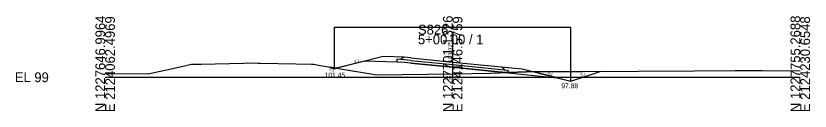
# Model space of a CAD drawing. Extents: x 2118382 to 2118616, y 1213030 to 1222057.
# Drawn here: x 2118381.9 to 2118610.4, y 1215530.1 to 1215557.4 of the extents above; entities that cross this region are included whole.
import ezdxf

# ---------------------------------------------------------------- set-up
doc = ezdxf.new("R2010")
doc.units = 0
for name, color, linetype in [('XS_CELL', 7, 'Continuous'), ('XS_M_DITCH', 7, 'Continuous'), ('XS_M_SHAPES_EARTHWORK', 7, 'Continuous'), ('XS_P_FINISHED_GRADE', 7, 'Continuous'), ('XS_P_FINISHED_GRADE_ELEV_TX', 7, 'Continuous'), ('XS_P_SUBGRADE_GRANULAR', 7, 'Continuous'), ('XS_P_SUBGRADE_PAVEMENT', 7, 'Continuous'), ('XS_P_TX_DCH', 7, 'Continuous'), ('XS_P_TX_FS_BS', 7, 'Continuous'), ('XS_X_GROUND', 7, 'Continuous'), ('XS_X_GROUND_TX', 7, 'Continuous')]:
    doc.layers.add(name, color=color, linetype=linetype)

msp = doc.modelspace()

# ---------------------------------------------------------------- linework, layer by layer
at = {"layer": 'XS_CELL'}
for p, q in [((2118507.6, 1215539.8), (2118507.6, 1215552.06)), ((2118407.6, 1215539.8), (2118507.6, 1215539.8)), ((2118507.6, 1215539.8), (2118607.6, 1215539.8))]:
    msp.add_line(p, q, dxfattribs=at)
at = {"layer": 'XS_M_DITCH'}
for p, q in [((2118473.6, 1215542.26), (2118473.6, 1215554.17)), ((2118473.6, 1215554.17), (2118541.6, 1215554.17)), ((2118541.6, 1215538.68), (2118541.6, 1215554.17))]:
    msp.add_line(p, q, dxfattribs=at)
at = {"layer": 'XS_M_SHAPES_EARTHWORK'}
for p, q in [((2118482.24, 1215544.41), (2118474.17, 1215542.4)), ((2118491.6, 1215544.13), (2118482.24, 1215544.41)), ((2118472.16, 1215542.74), (2118473.6, 1215542.26)), ((2118474.17, 1215542.4), (2118472.16, 1215542.74)), ((2118473.6, 1215542.26), (2118474.17, 1215542.4)), ((2118474.17, 1215542.4), (2118485.78, 1215540.45)), ((2118493.6, 1215544.07), (2118491.6, 1215544.13)), ((2118495.6, 1215543.87), (2118493.6, 1215544.07)), ((2118507.6, 1215542.67), (2118495.6, 1215543.87)), ((2118519.6, 1215541.47), (2118507.6, 1215542.67)), ((2118485.78, 1215540.45), (2118507.6, 1215540.82)), ((2118507.6, 1215540.82), (2118518.48, 1215541.01)), ((2118518.48, 1215541.01), (2118522.86, 1215541.15)), ((2118521.6, 1215541.27), (2118519.6, 1215541.47)), ((2118522.86, 1215541.15), (2118521.6, 1215541.27)), ((2118523.6, 1215541.17), (2118522.86, 1215541.15)), ((2118522.86, 1215541.15), (2118523.6, 1215541.07)), ((2118528.86, 1215541.34), (2118523.6, 1215541.17)), ((2118523.6, 1215541.07), (2118523.6, 1215541.17)), ((2118523.6, 1215541.17), (2118523.6, 1215541.07)), ((2118523.6, 1215541.07), (2118537.63, 1215539.67)), ((2118530.9, 1215541.35), (2118528.86, 1215541.34)), ((2118550.02, 1215541.48), (2118530.9, 1215541.35)), ((2118537.63, 1215539.67), (2118530.9, 1215541.35)), ((2118541.6, 1215538.68), (2118550.02, 1215541.48))]:
    msp.add_line(p, q, dxfattribs=at)
msp.add_lwpolyline([(2118530.9, 1215541.35), (2118537.63, 1215539.67), (2118541.6, 1215538.68)], dxfattribs=at)
at = {"layer": 'XS_P_FINISHED_GRADE'}
for p, q in [((2118487.6, 1215545.75), (2118473.6, 1215542.26)), ((2118493.6, 1215545.57), (2118487.6, 1215545.75)), ((2118495.6, 1215545.37), (2118493.6, 1215545.57)), ((2118495.6, 1215545.37), (2118507.6, 1215544.17)), ((2118473.6, 1215542.26), (2118472.16, 1215542.74)), ((2118507.6, 1215544.17), (2118519.6, 1215542.97)), ((2118519.6, 1215542.97), (2118521.6, 1215542.77)), ((2118521.6, 1215542.77), (2118527.6, 1215542.17)), ((2118527.6, 1215542.17), (2118541.6, 1215538.68)), ((2118541.6, 1215538.68), (2118550.02, 1215541.48))]:
    msp.add_line(p, q, dxfattribs=at)
at = {"layer": 'XS_P_SUBGRADE_GRANULAR'}
for p, q in [((2118491.6, 1215544.13), (2118482.24, 1215544.41)), ((2118491.6, 1215544.13), (2118491.6, 1215544.95)), ((2118492.71, 1215544.91), (2118491.6, 1215544.95)), ((2118493.6, 1215544.07), (2118491.6, 1215544.13)), ((2118495.6, 1215543.87), (2118493.6, 1215544.07)), ((2118495.6, 1215543.87), (2118507.6, 1215542.67)), ((2118507.6, 1215542.67), (2118519.6, 1215541.47)), ((2118519.6, 1215541.47), (2118521.6, 1215541.27)), ((2118521.6, 1215541.27), (2118523.6, 1215541.07)), ((2118522.42, 1215541.94), (2118523.6, 1215541.82)), ((2118523.6, 1215541.07), (2118523.6, 1215541.82)), ((2118523.6, 1215541.07), (2118537.63, 1215539.67))]:
    msp.add_line(p, q, dxfattribs=at)
at = {"layer": 'XS_P_SUBGRADE_PAVEMENT'}
for p, q in [((2118492.87, 1215545.19), (2118492.71, 1215544.91)), ((2118495.6, 1215544.62), (2118492.71, 1215544.91)), ((2118493.6, 1215545.57), (2118492.87, 1215545.19)), ((2118495.6, 1215544.62), (2118507.6, 1215543.42)), ((2118507.6, 1215543.42), (2118519.6, 1215542.22)), ((2118519.6, 1215542.22), (2118522.42, 1215541.94)), ((2118521.6, 1215542.77), (2118522.24, 1215542.25)), ((2118522.24, 1215542.25), (2118522.42, 1215541.94))]:
    msp.add_line(p, q, dxfattribs=at)
at = {"layer": 'XS_X_GROUND'}
for p, q in [((2118420, 1215540.79), (2118428.32, 1215542.63)), ((2118428.32, 1215542.63), (2118432.47, 1215543.56)), ((2118432.47, 1215543.56), (2118435.25, 1215543.58)), ((2118435.25, 1215543.58), (2118447.44, 1215543.86)), ((2118447.44, 1215543.86), (2118448.52, 1215543.89)), ((2118448.52, 1215543.89), (2118451.57, 1215543.84)), ((2118451.57, 1215543.84), (2118452.19, 1215543.83)), ((2118452.19, 1215543.83), (2118462.48, 1215543.67)), ((2118462.48, 1215543.67), (2118466.97, 1215543.53)), ((2118466.97, 1215543.53), (2118467.62, 1215543.51)), ((2118467.62, 1215543.51), (2118468.96, 1215543.27)), ((2118468.96, 1215543.27), (2118485.78, 1215540.45)), ((2118407.6, 1215540.92), (2118420, 1215540.79)), ((2118485.78, 1215540.45), (2118507.6, 1215540.82)), ((2118507.6, 1215540.82), (2118518.48, 1215541.01)), ((2118518.48, 1215541.01), (2118528.86, 1215541.34)), ((2118528.86, 1215541.34), (2118577.21, 1215541.67)), ((2118577.21, 1215541.67), (2118588.88, 1215541.73)), ((2118588.88, 1215541.73), (2118592.52, 1215541.74)), ((2118592.52, 1215541.74), (2118596.6, 1215541.72)), ((2118596.6, 1215541.72), (2118607.6, 1215541.69))]:
    msp.add_line(p, q, dxfattribs=at)

# ---------------------------------------------------------------- texts
at = {"layer": 'XS_CELL'}
for s, p in [('N 1227646.9964', (2118407.6, 1215529.8)), ('E 2124062.4969', (2118410.4, 1215529.8)), ('N 1227701.1326', (2118507.6, 1215529.8)), ('E 2124146.5759', (2118510.4, 1215529.8)), ('N 1227755.2688', (2118607.6, 1215529.8)), ('E 2124230.6548', (2118610.4, 1215529.8))]:
    msp.add_text(s, height=2.8, rotation=90, dxfattribs=at).set_placement(p)
for s, p in [('S826', (2118497.6, 1215552.06)), ('5+00.00 / 1', (2118497.6, 1215549.26)), ('EL 99', (2118381.6, 1215538.4))]:
    msp.add_text(s, height=2.8, dxfattribs=at).set_placement(p)
at = {"layer": 'XS_P_FINISHED_GRADE_ELEV_TX'}
msp.add_text('103.37', height=1.25, rotation=90, dxfattribs=at).set_placement((2118507.6, 1215543.98))
at = {"layer": 'XS_P_TX_DCH'}
for s, p in [('101.45', (2118470.76, 1215539.75)), ('97.88', (2118538.86, 1215536.65))]:
    msp.add_text(s, height=1.4, dxfattribs=at).set_placement(p)
at = {"layer": 'XS_P_TX_FS_BS'}
for s, rotation, p in [('4:1', 14.0188, (2118479.3, 1215543.88)), ('3:1', 341.5651, (2118471.92, 1215541.87)), ('3:1', 341.5651, (2118471.92, 1215541.87)), ('4:1', 345.9847, (2118534.85, 1215540.6)), ('3:1', 18.4082, (2118544.5, 1215539.98))]:
    msp.add_text(s, height=0.8, rotation=rotation, dxfattribs=at).set_placement(p)
at = {"layer": 'XS_X_GROUND_TX'}
msp.add_text('100.02', height=1, dxfattribs=at).set_placement((2118505.66, 1215539.21))

doc.saveas('drawing.dxf')
